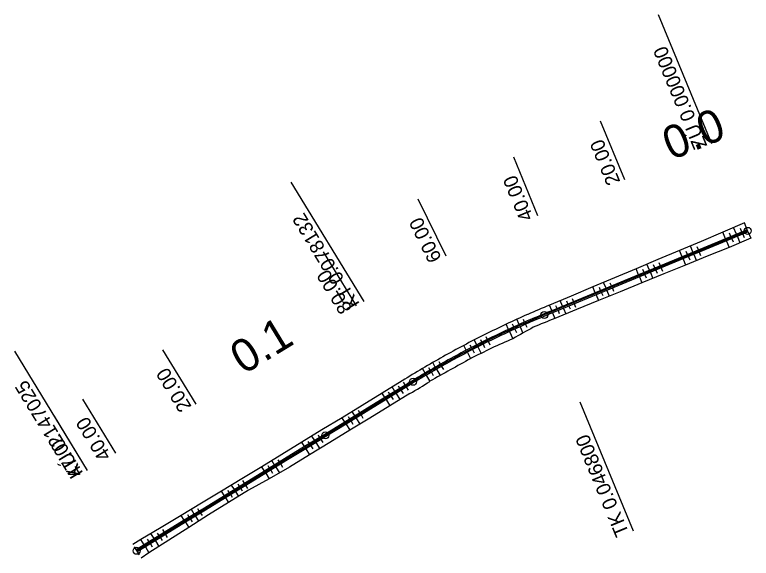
# Model space of a CAD drawing. Extents: x -481685 to -479315, y -1112639 to -1112242.
# Drawn here: x -479471.5 to -479314.9, y -1112357.2 to -1112241.7 of the extents above; entities that cross this region are included whole.
import ezdxf

# ---------------------------------------------------------------- set-up
doc = ezdxf.new("R2010")
doc.units = 0
for name, color, linetype in [('CP1_HATCH_SLOPE_L', 7, 'Continuous'), ('CP1_HATCH_SLOPE_R', 7, 'Continuous'), ('CP1_HECTOMETRY', 7, 'Continuous'), ('CP1_HLBODY', 7, 'Continuous'), ('CP1_HRANA_TELESO', 7, 'Continuous'), ('CP1_OSA', 7, 'Continuous'), ('CP1_STANICENI', 7, 'Continuous'), ('CP1_VOZOVKA', 7, 'Continuous'), ('CP1_ZPEVKRAJ', 7, 'Continuous')]:
    doc.layers.add(name, color=color, linetype=linetype)

msp = doc.modelspace()

# ---------------------------------------------------------------- linework, layer by layer
at = {"layer": 'CP1_HATCH_SLOPE_L'}
for p, q in [((-479315.51, -1112287.83), (-479314.96, -1112289.16)), ((-479318.98, -1112289.26), (-479318.7, -1112289.93)), ((-479317.82, -1112288.78), (-479317.27, -1112290.12)), ((-479316.67, -1112288.31), (-479316.39, -1112288.98)), ((-479320.13, -1112289.74), (-479319.58, -1112291.09)), ((-479325.91, -1112292.13), (-479325.64, -1112292.79)), ((-479329.37, -1112293.56), (-479328.84, -1112294.86)), ((-479328.22, -1112293.08), (-479327.95, -1112293.74)), ((-479327.06, -1112292.6), (-479326.52, -1112293.92)), ((-479325.36, -1112293.45), (-479325.36, -1112293.45)), ((-479327.68, -1112294.39), (-479327.68, -1112294.39)), ((-479337.46, -1112296.9), (-479337.2, -1112297.53)), ((-479336.3, -1112296.42), (-479335.78, -1112297.69)), ((-479335.15, -1112295.95), (-479334.89, -1112296.58)), ((-479334.62, -1112297.22), (-479334.62, -1112297.22)), ((-479338.61, -1112297.38), (-479338.1, -1112298.64)), ((-479336.94, -1112298.17), (-479336.94, -1112298.17)), ((-479345.55, -1112300.24), (-479345.04, -1112301.46)), ((-479344.39, -1112299.77), (-479344.14, -1112300.38)), ((-479347.86, -1112301.2), (-479347.36, -1112302.41)), ((-479346.7, -1112300.72), (-479346.45, -1112301.33)), ((-479346.2, -1112301.94), (-479346.2, -1112301.94)), ((-479343.88, -1112300.99), (-479343.88, -1112300.99)), ((-479357.1, -1112305.02), (-479356.62, -1112306.18)), ((-479355.94, -1112304.54), (-479355.7, -1112305.12)), ((-479354.79, -1112304.06), (-479354.3, -1112305.24)), ((-479353.63, -1112303.58), (-479353.39, -1112304.17)), ((-479353.15, -1112304.76), (-479353.15, -1112304.76)), ((-479355.46, -1112305.71), (-479355.46, -1112305.71)), ((-479363.99, -1112307.95), (-479363.4, -1112309.29)), ((-479362.85, -1112307.45), (-479362.58, -1112308.06)), ((-479366.27, -1112308.99), (-479365.56, -1112310.52)), ((-479365.13, -1112308.47), (-479364.8, -1112309.18)), ((-479362.31, -1112308.68), (-479362.31, -1112308.68)), ((-479364.48, -1112309.9), (-479364.48, -1112309.9)), ((-479374.11, -1112312.82), (-479373.77, -1112313.5)), ((-479373, -1112312.26), (-479372.31, -1112313.61)), ((-479371.89, -1112311.69), (-479371.55, -1112312.38)), ((-479375.22, -1112313.4), (-479374.53, -1112314.73)), ((-479373.42, -1112314.17), (-479373.42, -1112314.17)), ((-479371.2, -1112313.06), (-479371.2, -1112313.06)), ((-479381.79, -1112317), (-479381.03, -1112318.33)), ((-479380.7, -1112316.39), (-479380.32, -1112317.06)), ((-479383.95, -1112318.26), (-479383.18, -1112319.56)), ((-479382.87, -1112317.63), (-479382.49, -1112318.29)), ((-479382.1, -1112318.95), (-479382.1, -1112318.95)), ((-479379.95, -1112317.73), (-479379.95, -1112317.73)), ((-479390.36, -1112322.15), (-479389.56, -1112323.44)), ((-479389.29, -1112321.49), (-479388.89, -1112322.14)), ((-479392.49, -1112323.45), (-479391.7, -1112324.75)), ((-479391.42, -1112322.8), (-479391.03, -1112323.45)), ((-479388.5, -1112322.79), (-479388.5, -1112322.79)), ((-479390.63, -1112324.1), (-479390.63, -1112324.1)), ((-479397.82, -1112326.71), (-479397.42, -1112327.36)), ((-479399.96, -1112328.01), (-479399.56, -1112328.67)), ((-479398.89, -1112327.36), (-479398.09, -1112328.67)), ((-479397.03, -1112328.01), (-479397.03, -1112328.01)), ((-479401.02, -1112328.66), (-479400.22, -1112329.97)), ((-479399.16, -1112329.32), (-479399.16, -1112329.32)), ((-479408.49, -1112333.23), (-479408.09, -1112333.88)), ((-479407.42, -1112332.57), (-479406.62, -1112333.88)), ((-479406.36, -1112331.92), (-479405.96, -1112332.58)), ((-479405.56, -1112333.23), (-479405.56, -1112333.23)), ((-479409.55, -1112333.88), (-479408.76, -1112335.18)), ((-479407.69, -1112334.53), (-479407.69, -1112334.53)), ((-479415.96, -1112337.79), (-479415.2, -1112339.02)), ((-479414.89, -1112337.14), (-479414.5, -1112337.77)), ((-479418.09, -1112339.09), (-479417.36, -1112340.28)), ((-479417.02, -1112338.44), (-479416.65, -1112339.05)), ((-479414.12, -1112338.4), (-479414.12, -1112338.4)), ((-479416.28, -1112339.65), (-479416.28, -1112339.65)), ((-479423.42, -1112342.35), (-479423.12, -1112342.85)), ((-479425.55, -1112343.66), (-479425.25, -1112344.15)), ((-479424.49, -1112343), (-479423.88, -1112344)), ((-479422.81, -1112343.35), (-479422.81, -1112343.35)), ((-479426.62, -1112344.31), (-479426.02, -1112345.29)), ((-479424.95, -1112344.64), (-479424.95, -1112344.64)), ((-479434.09, -1112348.87), (-479433.76, -1112349.41)), ((-479433.02, -1112348.22), (-479432.38, -1112349.27)), ((-479431.95, -1112347.57), (-479431.64, -1112348.08)), ((-479431.32, -1112348.6), (-479431.32, -1112348.6)), ((-479435.15, -1112349.52), (-479434.48, -1112350.63)), ((-479433.43, -1112349.95), (-479433.43, -1112349.95)), ((-479441.55, -1112353.43), (-479440.82, -1112354.63)), ((-479440.49, -1112352.78), (-479440.13, -1112353.37)), ((-479443.69, -1112354.74), (-479442.92, -1112355.98)), ((-479442.62, -1112354.08), (-479442.25, -1112354.7)), ((-479439.77, -1112353.96), (-479439.77, -1112353.96)), ((-479441.87, -1112355.31), (-479441.87, -1112355.31))]:
    msp.add_line(p, q, dxfattribs=at)
at = {"layer": 'CP1_HATCH_SLOPE_R'}
for p, q in [((-479315.71, -1112287.35), (-479316.31, -1112285.89)), ((-479318.02, -1112288.3), (-479318.61, -1112286.88)), ((-479316.86, -1112287.83), (-479317.16, -1112287.11)), ((-479320.33, -1112289.26), (-479320.91, -1112287.87)), ((-479319.17, -1112288.78), (-479319.47, -1112288.08)), ((-479327.26, -1112292.12), (-479327.81, -1112290.79)), ((-479326.66, -1112290.3), (-479326.66, -1112290.3)), ((-479326.11, -1112291.65), (-479326.38, -1112290.98)), ((-479329.57, -1112293.08), (-479330.12, -1112291.75)), ((-479328.97, -1112291.27), (-479328.97, -1112291.27)), ((-479328.42, -1112292.6), (-479328.69, -1112291.94)), ((-479338.81, -1112296.9), (-479339.34, -1112295.62)), ((-479338.19, -1112295.14), (-479338.19, -1112295.14)), ((-479336.5, -1112295.94), (-479337.04, -1112294.65)), ((-479335.88, -1112294.17), (-479335.88, -1112294.17)), ((-479335.35, -1112295.47), (-479335.62, -1112294.82)), ((-479337.66, -1112296.42), (-479337.92, -1112295.78)), ((-479345.74, -1112299.76), (-479346.25, -1112298.53)), ((-479345.1, -1112298.05), (-479345.1, -1112298.05)), ((-479344.59, -1112299.28), (-479344.85, -1112298.67)), ((-479348.06, -1112300.72), (-479348.56, -1112299.51)), ((-479347.4, -1112299.02), (-479347.4, -1112299.02)), ((-479346.9, -1112300.24), (-479347.15, -1112299.63)), ((-479354.32, -1112301.93), (-479354.32, -1112301.93)), ((-479357.3, -1112304.54), (-479357.78, -1112303.38)), ((-479356.62, -1112302.89), (-479356.62, -1112302.89)), ((-479356.14, -1112304.06), (-479356.38, -1112303.48)), ((-479354.99, -1112303.58), (-479355.47, -1112302.41)), ((-479353.83, -1112303.1), (-479354.08, -1112302.51)), ((-479364.2, -1112307.48), (-479364.7, -1112306.37)), ((-479363.55, -1112305.85), (-479363.55, -1112305.85)), ((-479363.06, -1112306.97), (-479363.31, -1112306.41)), ((-479366.48, -1112308.52), (-479366.99, -1112307.42)), ((-479365.85, -1112306.89), (-479365.85, -1112306.89)), ((-479365.35, -1112307.99), (-479365.6, -1112307.44)), ((-479374.88, -1112311.33), (-479374.88, -1112311.33)), ((-479373.24, -1112311.79), (-479373.77, -1112310.76)), ((-479372.65, -1112310.18), (-479372.65, -1112310.18)), ((-479372.12, -1112311.23), (-479372.38, -1112310.71)), ((-479375.46, -1112312.94), (-479376, -1112311.92)), ((-479374.35, -1112312.36), (-479374.62, -1112311.85)), ((-479382.05, -1112316.55), (-479382.6, -1112315.58)), ((-479381.51, -1112314.96), (-479381.51, -1112314.96)), ((-479380.96, -1112315.93), (-479381.24, -1112315.45)), ((-479384.21, -1112317.81), (-479384.78, -1112316.86)), ((-479383.69, -1112316.22), (-479383.69, -1112316.22)), ((-479383.13, -1112317.18), (-479383.41, -1112316.7)), ((-479390.14, -1112320.11), (-479390.14, -1112320.11)), ((-479389.56, -1112321.05), (-479389.85, -1112320.58)), ((-479392.76, -1112323.01), (-479393.34, -1112322.06)), ((-479392.27, -1112321.41), (-479392.27, -1112321.41)), ((-479391.69, -1112322.35), (-479391.98, -1112321.88)), ((-479390.63, -1112321.7), (-479391.21, -1112320.76)), ((-479398.67, -1112325.32), (-479398.67, -1112325.32)), ((-479400.8, -1112326.62), (-479400.8, -1112326.62)), ((-479399.16, -1112326.92), (-479399.74, -1112325.97)), ((-479398.09, -1112326.26), (-479398.38, -1112325.79)), ((-479401.29, -1112328.22), (-479401.87, -1112327.28)), ((-479400.23, -1112327.57), (-479400.52, -1112327.1)), ((-479407.69, -1112332.13), (-479408.27, -1112331.19)), ((-479407.2, -1112330.54), (-479407.2, -1112330.54)), ((-479406.63, -1112331.48), (-479406.91, -1112331.01)), ((-479409.83, -1112333.43), (-479410.4, -1112332.49)), ((-479409.34, -1112331.84), (-479409.34, -1112331.84)), ((-479408.76, -1112332.78), (-479409.05, -1112332.31)), ((-479415.73, -1112335.75), (-479415.73, -1112335.75)), ((-479415.16, -1112336.69), (-479415.45, -1112336.22)), ((-479418.36, -1112338.65), (-479418.93, -1112337.71)), ((-479417.87, -1112337.06), (-479417.87, -1112337.06)), ((-479417.29, -1112338), (-479417.58, -1112337.53)), ((-479416.23, -1112337.34), (-479416.8, -1112336.41)), ((-479424.28, -1112340.95), (-479424.28, -1112340.95)), ((-479426.42, -1112342.25), (-479426.42, -1112342.25)), ((-479424.76, -1112342.56), (-479425.35, -1112341.6)), ((-479423.69, -1112341.91), (-479423.98, -1112341.43)), ((-479426.89, -1112343.86), (-479427.48, -1112342.89)), ((-479425.83, -1112343.21), (-479426.12, -1112342.73)), ((-479433.29, -1112347.77), (-479433.91, -1112346.76)), ((-479432.84, -1112346.12), (-479432.84, -1112346.12)), ((-479432.23, -1112347.12), (-479432.53, -1112346.62)), ((-479435.42, -1112349.08), (-479436.06, -1112348.04)), ((-479434.99, -1112347.4), (-479434.99, -1112347.4)), ((-479434.36, -1112348.43), (-479434.67, -1112347.91)), ((-479441.83, -1112352.99), (-479442.5, -1112351.88)), ((-479441.43, -1112351.24), (-479441.43, -1112351.24)), ((-479440.76, -1112352.34), (-479441.09, -1112351.79)), ((-479443.96, -1112354.29), (-479444.65, -1112353.17)), ((-479443.57, -1112352.52), (-479443.57, -1112352.52)), ((-479442.89, -1112353.64), (-479443.23, -1112353.08))]:
    msp.add_line(p, q, dxfattribs=at)
at = {"layer": 'CP1_HECTOMETRY'}
for centre in [(-479315.61, -1112287.59), (-479405.42, -1112331.05)]:
    msp.add_circle(centre, 0.75, dxfattribs=at)
at = {"layer": 'CP1_HLBODY'}
for p, q in [((-479323.25, -1112269.11), (-479334.59, -1112241.66)), ((-479397.19, -1112302.58), (-479412.68, -1112277.24)), ((-479455.98, -1112338.5), (-479471.47, -1112313.16)), ((-479339.88, -1112351.4), (-479351.22, -1112323.95))]:
    msp.add_line(p, q, dxfattribs=at)
for centre in [(-479315.61, -1112287.59), (-479358.86, -1112305.46), (-479386.77, -1112319.65), (-479445.55, -1112355.57)]:
    msp.add_circle(centre, 0.75, dxfattribs=at)
at = {"layer": 'CP1_HRANA_TELESO'}
for p, q in [((-479316.31, -1112285.89), (-479320.91, -1112287.87)), ((-479320.91, -1112287.87), (-479325.51, -1112289.82)), ((-479314.96, -1112289.16), (-479319.58, -1112291.09)), ((-479325.51, -1112289.82), (-479330.12, -1112291.75)), ((-479330.12, -1112291.75), (-479334.73, -1112293.69)), ((-479319.58, -1112291.09), (-479324.21, -1112292.98)), ((-479334.73, -1112293.69), (-479339.34, -1112295.62)), ((-479324.21, -1112292.98), (-479328.84, -1112294.86)), ((-479339.34, -1112295.62), (-479343.95, -1112297.56)), ((-479328.84, -1112294.86), (-479333.47, -1112296.75)), ((-479333.47, -1112296.75), (-479338.1, -1112298.64)), ((-479343.95, -1112297.56), (-479348.56, -1112299.51)), ((-479338.1, -1112298.64), (-479342.73, -1112300.52)), ((-479348.56, -1112299.51), (-479353.17, -1112301.44)), ((-479353.17, -1112301.44), (-479357.78, -1112303.38)), ((-479342.73, -1112300.52), (-479347.36, -1112302.41)), ((-479347.36, -1112302.41), (-479351.99, -1112304.29)), ((-479351.99, -1112304.29), (-479356.62, -1112306.18)), ((-479389.07, -1112319.45), (-479393.34, -1112322.06)), ((-479393.34, -1112322.06), (-479397.6, -1112324.67)), ((-479387.43, -1112322.14), (-479391.7, -1112324.75)), ((-479397.6, -1112324.67), (-479401.87, -1112327.28)), ((-479391.7, -1112324.75), (-479395.96, -1112327.36)), ((-479401.87, -1112327.28), (-479406.14, -1112329.89)), ((-479395.96, -1112327.36), (-479400.22, -1112329.97)), ((-479406.14, -1112329.89), (-479410.4, -1112332.49)), ((-479400.22, -1112329.97), (-479404.49, -1112332.58)), ((-479410.4, -1112332.49), (-479414.67, -1112335.1)), ((-479404.49, -1112332.58), (-479408.76, -1112335.18)), ((-479414.67, -1112335.1), (-479418.93, -1112337.71)), ((-479408.76, -1112335.18), (-479413.04, -1112337.77)), ((-479418.93, -1112337.71), (-479423.21, -1112340.3)), ((-479413.04, -1112337.77), (-479417.36, -1112340.28)), ((-479423.21, -1112340.3), (-479427.48, -1112342.89)), ((-479417.36, -1112340.28), (-479421.74, -1112342.71)), ((-479427.48, -1112342.89), (-479431.77, -1112345.48)), ((-479421.74, -1112342.71), (-479426.02, -1112345.29)), ((-479431.77, -1112345.48), (-479436.06, -1112348.04)), ((-479426.02, -1112345.29), (-479430.27, -1112347.92)), ((-479436.06, -1112348.04), (-479440.35, -1112350.6)), ((-479430.27, -1112347.92), (-479434.48, -1112350.63)), ((-479440.35, -1112350.6), (-479444.65, -1112353.17)), ((-479434.48, -1112350.63), (-479438.72, -1112353.28)), ((-479444.65, -1112353.17), (-479446.38, -1112354.2)), ((-479438.72, -1112353.28), (-479442.92, -1112355.98)), ((-479442.92, -1112355.98), (-479444.58, -1112357.16))]:
    msp.add_line(p, q, dxfattribs=at)
for centre, radius, start, end in [((-479123.47, -1112860.59), 604.47, 112.80623, 113.28244), ((-479281.48, -1112489.85), 201.48, 113.6816, 115.114), ((-479131.02, -1112857.31), 595.52, 112.26163, 112.74037), ((-479281.46, -1112489.82), 201.45, 115.1222, 116.5546), ((-479266.43, -1112482.24), 198.28, 118.5562, 119.9945), ((-479281.57, -1112489.84), 201.42, 116.5231, 117.9555), ((-479287.63, -1112492.67), 198.13, 113.1614, 114.5944), ((-479281.59, -1112489.82), 201.4, 117.9543, 119.3867), ((-479283.96, -1112491.05), 198.22, 115.7538, 117.1862), ((-479281.86, -1112489.95), 201.38, 119.3016, 120.734), ((-479280.68, -1112489.32), 198.21, 118.2574, 119.6898), ((-479334.84, -1112404.29), 100.68, 119.7297, 122.5875), ((-479283.71, -1112491), 198.21, 118.6897, 120.1221), ((-479436.61, -1112236.09), 99.11, 299.7454, 302.62)]:
    msp.add_arc(centre, radius, start, end, dxfattribs=at)
at = {"layer": 'CP1_OSA'}
for p, q in [((-479315.61, -1112287.59), (-479358.86, -1112305.46)), ((-479386.77, -1112319.65), (-479445.55, -1112355.57))]:
    msp.add_line(p, q, dxfattribs=at)
msp.add_arc((-479282.48, -1112490.3), 200, 112.4534, 121.4296, dxfattribs=at)
at = {"layer": 'CP1_STANICENI'}
for p, q in [((-479341.73, -1112276.75), (-479346.89, -1112264.27)), ((-479360.22, -1112284.38), (-479365.37, -1112271.91)), ((-479379.73, -1112292.97), (-479385.7, -1112280.86)), ((-479398.79, -1112303.55), (-479405.83, -1112292.03)), ((-479334.48, -1112294.3), (-479333.71, -1112296.15)), ((-479352.96, -1112301.94), (-479352.2, -1112303.79)), ((-479371.33, -1112310.01), (-479370.44, -1112311.8)), ((-479432.92, -1112324.41), (-479439.96, -1112312.89)), ((-479388.88, -1112319.77), (-479387.84, -1112321.47)), ((-479449.98, -1112334.84), (-479457.02, -1112323.32)), ((-479455.98, -1112338.5), (-479463.02, -1112326.98)), ((-479423.01, -1112340.62), (-479421.97, -1112342.33)), ((-479440.08, -1112351.05), (-479439.03, -1112352.76)), ((-479446.07, -1112354.71), (-479445.02, -1112356.42))]:
    msp.add_line(p, q, dxfattribs=at)
at = {"layer": 'CP1_VOZOVKA'}
for p, q in [((-479315.71, -1112287.36), (-479320.33, -1112289.27)), ((-479315.52, -1112287.82), (-479320.14, -1112289.73)), ((-479320.33, -1112289.27), (-479324.95, -1112291.18)), ((-479320.14, -1112289.73), (-479324.76, -1112291.64)), ((-479324.95, -1112291.18), (-479329.57, -1112293.09)), ((-479324.76, -1112291.64), (-479329.38, -1112293.55)), ((-479329.57, -1112293.09), (-479334.19, -1112295)), ((-479329.38, -1112293.55), (-479334, -1112295.46)), ((-479334.19, -1112295), (-479338.81, -1112296.91)), ((-479334, -1112295.46), (-479338.62, -1112297.37)), ((-479338.81, -1112296.91), (-479343.43, -1112298.82)), ((-479338.62, -1112297.37), (-479343.24, -1112299.28)), ((-479343.43, -1112298.82), (-479348.05, -1112300.73)), ((-479343.24, -1112299.28), (-479347.86, -1112301.19)), ((-479348.05, -1112300.73), (-479352.67, -1112302.64)), ((-479347.86, -1112301.19), (-479352.48, -1112303.1)), ((-479352.67, -1112302.64), (-479357.29, -1112304.55)), ((-479352.48, -1112303.1), (-479357.1, -1112305.01)), ((-479388.49, -1112320.41), (-479392.76, -1112323.01)), ((-479388.23, -1112320.83), (-479392.49, -1112323.44)), ((-479392.76, -1112323.01), (-479397.02, -1112325.62)), ((-479392.49, -1112323.44), (-479396.76, -1112326.05)), ((-479397.02, -1112325.62), (-479401.29, -1112328.23)), ((-479396.76, -1112326.05), (-479401.03, -1112328.66)), ((-479401.29, -1112328.23), (-479405.55, -1112330.84)), ((-479401.03, -1112328.66), (-479405.29, -1112331.26)), ((-479405.55, -1112330.84), (-479409.82, -1112333.44)), ((-479405.29, -1112331.26), (-479409.56, -1112333.87)), ((-479409.82, -1112333.44), (-479414.09, -1112336.05)), ((-479409.56, -1112333.87), (-479413.83, -1112336.48)), ((-479414.09, -1112336.05), (-479418.35, -1112338.66)), ((-479413.83, -1112336.48), (-479418.09, -1112339.08)), ((-479418.35, -1112338.66), (-479422.62, -1112341.27)), ((-479418.09, -1112339.08), (-479422.36, -1112341.69)), ((-479422.62, -1112341.27), (-479426.89, -1112343.87)), ((-479422.36, -1112341.69), (-479426.63, -1112344.3)), ((-479426.89, -1112343.87), (-479431.15, -1112346.48)), ((-479426.63, -1112344.3), (-479430.89, -1112346.91)), ((-479431.15, -1112346.48), (-479435.42, -1112349.09)), ((-479430.89, -1112346.91), (-479435.16, -1112349.51)), ((-479435.42, -1112349.09), (-479439.69, -1112351.69)), ((-479435.16, -1112349.51), (-479439.43, -1112352.12)), ((-479439.69, -1112351.69), (-479443.95, -1112354.3)), ((-479439.43, -1112352.12), (-479443.69, -1112354.73)), ((-479443.95, -1112354.3), (-479445.68, -1112355.35)), ((-479443.69, -1112354.73), (-479445.42, -1112355.78))]:
    msp.add_line(p, q, dxfattribs=at)
for centre, radius, start, end in [((-479127.32, -1112859.53), 600.75, 112.50839, 112.98563), ((-479127.7, -1112858.61), 599.25, 112.50791, 112.98558), ((-479282.48, -1112490.3), 200.25, 113.3703, 114.8027), ((-479282.48, -1112490.3), 199.75, 113.3703, 114.8027), ((-479282.48, -1112490.3), 200.25, 114.8027, 116.2351), ((-479282.48, -1112490.3), 199.75, 114.8027, 116.2351), ((-479282.48, -1112490.3), 200.25, 116.2351, 117.6675), ((-479282.48, -1112490.3), 199.75, 116.2351, 117.6675), ((-479282.48, -1112490.3), 200.25, 117.6675, 119.0999), ((-479282.48, -1112490.3), 199.75, 117.6675, 119.0999), ((-479282.48, -1112490.3), 200.25, 119.0999, 120.5323), ((-479282.48, -1112490.3), 199.75, 119.0999, 120.5323), ((-479334.57, -1112404.78), 100.12, 119.7165, 122.5802), ((-479334.45, -1112404.99), 99.88, 119.7155, 122.5818)]:
    msp.add_arc(centre, radius, start, end, dxfattribs=at)
at = {"layer": 'CP1_ZPEVKRAJ'}
for p, q in [((-479315.71, -1112287.36), (-479320.33, -1112289.27)), ((-479315.52, -1112287.82), (-479320.14, -1112289.73)), ((-479320.33, -1112289.27), (-479324.95, -1112291.18)), ((-479320.14, -1112289.73), (-479324.76, -1112291.64)), ((-479324.95, -1112291.18), (-479329.57, -1112293.09)), ((-479324.76, -1112291.64), (-479329.38, -1112293.55)), ((-479329.57, -1112293.09), (-479334.19, -1112295)), ((-479329.38, -1112293.55), (-479334, -1112295.46)), ((-479334.19, -1112295), (-479338.81, -1112296.91)), ((-479334, -1112295.46), (-479338.62, -1112297.37)), ((-479338.81, -1112296.91), (-479343.43, -1112298.82)), ((-479338.62, -1112297.37), (-479343.24, -1112299.28)), ((-479343.43, -1112298.82), (-479348.05, -1112300.73)), ((-479343.24, -1112299.28), (-479347.86, -1112301.19)), ((-479348.05, -1112300.73), (-479352.67, -1112302.64)), ((-479347.86, -1112301.19), (-479352.48, -1112303.1)), ((-479352.67, -1112302.64), (-479357.29, -1112304.55)), ((-479352.48, -1112303.1), (-479357.1, -1112305.01)), ((-479388.49, -1112320.41), (-479392.76, -1112323.01)), ((-479388.23, -1112320.83), (-479392.49, -1112323.44)), ((-479392.76, -1112323.01), (-479397.02, -1112325.62)), ((-479392.49, -1112323.44), (-479396.76, -1112326.05)), ((-479397.02, -1112325.62), (-479401.29, -1112328.23)), ((-479396.76, -1112326.05), (-479401.03, -1112328.66)), ((-479401.29, -1112328.23), (-479405.55, -1112330.84)), ((-479401.03, -1112328.66), (-479405.29, -1112331.26)), ((-479405.55, -1112330.84), (-479409.82, -1112333.44)), ((-479405.29, -1112331.26), (-479409.56, -1112333.87)), ((-479409.82, -1112333.44), (-479414.09, -1112336.05)), ((-479409.56, -1112333.87), (-479413.83, -1112336.48)), ((-479414.09, -1112336.05), (-479418.35, -1112338.66)), ((-479413.83, -1112336.48), (-479418.09, -1112339.08)), ((-479418.35, -1112338.66), (-479422.62, -1112341.27)), ((-479418.09, -1112339.08), (-479422.36, -1112341.69)), ((-479422.62, -1112341.27), (-479426.89, -1112343.87)), ((-479422.36, -1112341.69), (-479426.63, -1112344.3)), ((-479426.89, -1112343.87), (-479431.15, -1112346.48)), ((-479426.63, -1112344.3), (-479430.89, -1112346.91)), ((-479431.15, -1112346.48), (-479435.42, -1112349.09)), ((-479430.89, -1112346.91), (-479435.16, -1112349.51)), ((-479435.42, -1112349.09), (-479439.69, -1112351.69)), ((-479435.16, -1112349.51), (-479439.43, -1112352.12)), ((-479439.69, -1112351.69), (-479443.95, -1112354.3)), ((-479439.43, -1112352.12), (-479443.69, -1112354.73)), ((-479443.95, -1112354.3), (-479445.68, -1112355.35)), ((-479443.69, -1112354.73), (-479445.42, -1112355.78))]:
    msp.add_line(p, q, dxfattribs=at)
for centre, radius, start, end in [((-479127.32, -1112859.53), 600.75, 112.50839, 112.98563), ((-479127.7, -1112858.61), 599.25, 112.50791, 112.98558), ((-479282.48, -1112490.3), 200.25, 113.3703, 114.8027), ((-479282.48, -1112490.3), 199.75, 113.3703, 114.8027), ((-479282.48, -1112490.3), 200.25, 114.8027, 116.2351), ((-479282.48, -1112490.3), 199.75, 114.8027, 116.2351), ((-479282.48, -1112490.3), 200.25, 116.2351, 117.6675), ((-479282.48, -1112490.3), 199.75, 116.2351, 117.6675), ((-479282.48, -1112490.3), 200.25, 117.6675, 119.0999), ((-479282.48, -1112490.3), 199.75, 117.6675, 119.0999), ((-479282.48, -1112490.3), 200.25, 119.0999, 120.5323), ((-479282.48, -1112490.3), 199.75, 119.0999, 120.5323), ((-479334.57, -1112404.78), 100.12, 119.7165, 122.5802), ((-479334.45, -1112404.99), 99.88, 119.7155, 122.5818)]:
    msp.add_arc(centre, radius, start, end, dxfattribs=at)

# ---------------------------------------------------------------- texts
at = {"layer": 'CP1_HECTOMETRY'}
for s, rotation, p in [('0.0', 22.4078, (-479331.86, -1112272.66)), ('0.1', 31.3839, (-479422.83, -1112318.24))]:
    msp.add_text(s, height=7, rotation=rotation, dxfattribs=at).set_placement(p)
at = {"layer": 'CP1_HLBODY'}
for s, height, rotation, p in [('ZÚ 0.000000', 3, 112.4534, (-479324.17, -1112269.49)), ('KT 0.078132', 2.999, 121.4296, (-479398.05, -1112303.1)), ('KÚ 0.147025', 2.999, 121.4296, (-479456.83, -1112339.03)), ('TK 0.046800', 3, 112.4534, (-479340.8, -1112351.78))]:
    msp.add_text(s, height=height, rotation=rotation, dxfattribs=at).set_placement(p)
at = {"layer": 'CP1_STANICENI'}
for s, height, rotation, p in [('20.00', 3, 112.4534, (-479342.66, -1112277.13)), ('40.00', 3, 112.4534, (-479361.14, -1112284.77)), ('60.00', 3, 116.2351, (-479380.62, -1112293.41)), ('80.00', 2.999, 121.4296, (-479399.64, -1112304.08)), ('20.00', 2.999, 121.4296, (-479433.77, -1112324.93)), ('40.00', 2.999, 121.4296, (-479450.84, -1112335.36)), ('47.02', 2.999, 121.4296, (-479456.83, -1112339.02))]:
    msp.add_text(s, height=height, rotation=rotation, dxfattribs=at).set_placement(p)

doc.saveas('drawing.dxf')
